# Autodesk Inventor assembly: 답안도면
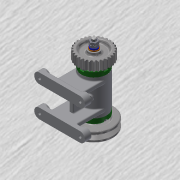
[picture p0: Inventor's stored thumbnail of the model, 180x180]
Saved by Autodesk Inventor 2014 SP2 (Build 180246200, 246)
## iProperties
Created: 2015-11
Part Number: 답안도면
Document SubType Name: Assembly
Designer: 702
Author: 702
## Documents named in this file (13)
- C:\Users\702\Desktop\451109V1008\답안도면.iam
- C:\Users\702\Desktop\451109V1008\본체.ipt
- C:\Users\702\Desktop\451109V1008\베어링 15 x 32 x 9.ipt
- C:\Users\702\Desktop\451109V1008\축.ipt
- C:\Users\702\Desktop\451109V1008\키 3 x 3 x 12.ipt
- C:\Users\702\Desktop\451109V1008\커버.ipt
- C:\Users\702\Desktop\451109V1008\볼트 M4 x 12.ipt
- C:\Users\702\Desktop\451109V1008\오일 실 15 25 7.ipt
- C:\Users\702\Desktop\451109V1008\V벨트풀리.ipt
- C:\Users\702\Desktop\451109V1008\스퍼기어.ipt
- C:\Users\702\Desktop\451109V1008\너트 M 8.ipt
- C:\Users\702\Desktop\451109V1008\스프링와셔 8.ipt
- C:\Users\702\Desktop\451109V1008\와셔 8x17.ipt
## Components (11 placed, 3 different names)
1. KS B 2023 6002 - 15 x 32 x 9:1
2. KS B 2023 6002 - 15 x 32 x 9:2
3. V벨트풀리:1
4. ISO 4762 M4 x 12:1
5. ISO 4762 M4 x 12:2
6. ISO 4762 M4 x 12:3
7. ISO 4762 M4 x 12:4
8. ISO 4762 M4 x 12:5
9. ISO 4762 M4 x 12:6
10. ISO 4762 M4 x 12:7
11. ISO 4762 M4 x 12:8
